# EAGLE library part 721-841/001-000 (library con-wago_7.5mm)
Serie 721, Stiftleiste (für Leiterplatten) Einlötstift abgewinkelt 1 x 1 mm / Series 721, Male header (for PCBs) Angled solder pin 1 x 1 mm Polzahl / Pole No.: 11 Rastermaß / Pitch: 7.5 mm Bemessungsspannung / Rated Voltage: 630 V Nennstrom / Nominal Current: 12 A Lötstiftlänge: / Solder Pin Length: 3.8 mm Farbe / Color: lichtgrau / light gray Stand: 01.01.2012. Die jeweils aktuellen Daten zu diesem Artikel finden Sie in unserem Produktkatalog, den Sie unter www.wago.com einsehen können. As of: 01/01/2012. Please find the newest data for this article in our product catalogue, which can be viewed under www.wago.com.
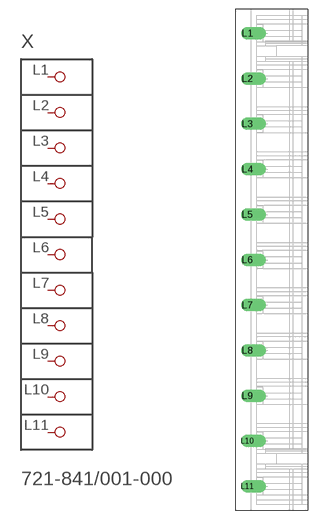
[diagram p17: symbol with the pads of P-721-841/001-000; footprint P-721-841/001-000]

Designator prefix X

## 721-841/001-000  [P-721-841/001-000]
L1  P1
L2  P2
L3  P3
L4  P4
L5  P5
L6  P6
L7  P7
L8  P8
L9  P9
L10  P10
L11  P11

## Footprint P-721-841/001-000 (pad centres in mm)
drill 1.4 offset: L1 -4,37.5; L2 -4,30; L3 -4,22.5; L4 -4,15; L5 -4,7.5; L6 -4,0; L7 -4,-7.5; L8 -4,-15; L9 -4,-22.5; L10 -4,-30; L11 -4,-37.5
